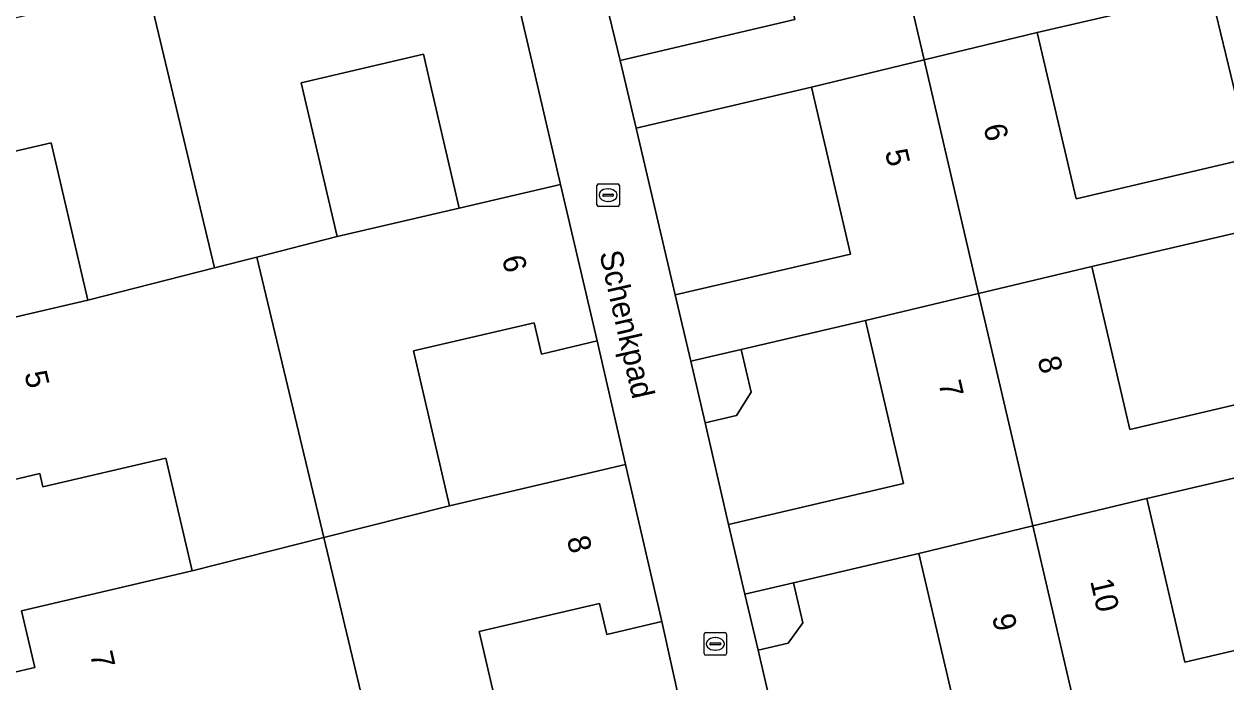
# Model space of a CAD drawing. Extents: x 162989 to 165008, y 383432 to 384338.
# Drawn here: x 164115.4 to 164168.7, y 384051 to 384080.1 of the extents above; entities that cross this region are included whole.
import ezdxf

# ---------------------------------------------------------------- set-up
doc = ezdxf.new("R2010")
doc.units = 0
for name, color, linetype in [('IMGEO_Erf', 7, 'Continuous'), ('IMGEO_Kolk', 7, 'Continuous'), ('IMGEO_Muur', 7, 'Continuous'), ('IMGEO_Openbare_ruimte_label', 7, 'Continuous'), ('IMGEO_Pand', 7, 'Continuous'), ('IMGEO_Pand_nummerreeks', 7, 'Continuous'), ('IMGEO_Voetpad_open', 7, 'Continuous')]:
    doc.layers.add(name, color=color, linetype=linetype)

msp = doc.modelspace()

# ---------------------------------------------------------------- linework, layer by layer
at = {"layer": 'IMGEO_Erf'}
for points in [[(164147.874, 384087.715), (164143.253, 384086.635), (164143.08, 384086.595), (164143.508, 384084.764), (164142.803, 384083.533), (164140.751, 384083.053), (164141.848, 384078.536), (164149.596, 384080.346)], [(164168.048, 384081.568), (164160.35, 384079.769), (164162.071, 384072.403), (164169.826, 384074.215)], [(164134.711, 384071.989), (164133.435, 384077.456), (164133.12, 384078.806), (164127.701, 384077.54), (164129.294, 384070.723)], [(164144.293, 384068.134), (164152.06, 384069.949), (164150.332, 384077.345), (164142.551, 384075.527)], [(164111.013, 384063.235), (164113.039, 384063.707), (164112.377, 384066.539), (164118.23, 384067.907), (164116.6, 384074.881), (164111.062, 384073.587), (164111.395, 384072.161), (164109.064, 384071.616)], [(164170.529, 384071.206), (164162.771, 384069.393), (164164.459, 384062.17), (164172.21, 384063.981)], [(164140.825, 384066.092), (164138.351, 384065.514), (164138.027, 384066.899), (164132.676, 384065.649), (164134.279, 384058.785), (164142.077, 384060.607)], [(164152.727, 384067.005), (164147.21, 384065.716), (164147.653, 384063.823), (164147.014, 384062.782), (164145.618, 384062.456), (164146.658, 384057.958), (164154.417, 384059.771)], [(164121.686, 384060.895), (164116.233, 384059.62), (164116.095, 384060.211), (164113.972, 384059.715), (164111.942, 384059.24), (164113.243, 384053.645), (164113.821, 384051.131), (164115.871, 384051.609), (164115.284, 384054.122), (164122.855, 384055.891)], [(164172.928, 384060.907), (164165.207, 384059.103), (164166.902, 384051.852), (164174.66, 384053.664)], [(164155.096, 384056.665), (164149.539, 384055.366), (164149.956, 384053.584), (164149.297, 384052.686), (164147.962, 384052.374), (164149.08, 384047.587), (164156.796, 384049.39)], [(164143.702, 384053.651), (164141.255, 384053.08), (164140.935, 384054.45), (164135.587, 384053.2), (164137.201, 384046.293), (164144.926, 384048.098)]]:
    msp.add_lwpolyline(points, close=True, dxfattribs=at)
at = {"layer": 'IMGEO_Kolk'}
for p, q in [((164140.813, 384072.134), (164140.813, 384072.986)), ((164140.888, 384073.06), (164141.74, 384073.06)), ((164141.072, 384072.554), (164141.072, 384072.566)), ((164141.115, 384072.603), (164141.513, 384072.603)), ((164141.301, 384072.84), (164141.326, 384072.84)), ((164141.556, 384072.566), (164141.556, 384072.554)), ((164141.814, 384072.986), (164141.814, 384072.134)), ((164141.74, 384072.06), (164140.888, 384072.06)), ((164141.51, 384072.517), (164141.112, 384072.517)), ((164141.324, 384072.28), (164141.299, 384072.28)), ((164145.567, 384052.23), (164145.567, 384053.082)), ((164145.642, 384053.156), (164146.494, 384053.156)), ((164146.055, 384052.936), (164146.08, 384052.936)), ((164146.568, 384053.082), (164146.568, 384052.23)), ((164145.826, 384052.65), (164145.826, 384052.662)), ((164146.264, 384052.613), (164145.866, 384052.613)), ((164145.869, 384052.699), (164146.267, 384052.699)), ((164146.078, 384052.376), (164146.053, 384052.376)), ((164146.31, 384052.662), (164146.31, 384052.65)), ((164146.494, 384052.156), (164145.642, 384052.156))]:
    msp.add_line(p, q, dxfattribs=at)
for points in [[(164140.813, 384072.134), (164140.813, 384072.986)], [(164140.888, 384073.06), (164141.74, 384073.06)], [(164141.814, 384072.986), (164141.814, 384072.134)], [(164141.74, 384072.06), (164140.888, 384072.06)], [(164145.567, 384052.23), (164145.567, 384053.082)], [(164145.642, 384053.156), (164146.494, 384053.156)], [(164146.568, 384053.082), (164146.568, 384052.23)], [(164146.494, 384052.156), (164145.642, 384052.156)]]:
    msp.add_lwpolyline(points, dxfattribs=at)
for centre, radius, start, end in [((164140.89, 384072.984), 0.0765, 91.552, 178.448), ((164140.89, 384072.984), 0.0765, 91.552, 178.448), ((164141.112, 384072.563), 0.0403, 85.8775, 175.7526), ((164141.109, 384072.553), 0.0366, 178.938, 274.7102), ((164141.513, 384072.56), 0.043, 264.8664, 352.4533), ((164141.517, 384072.565), 0.0386, 1.7309, 96.639), ((164141.738, 384072.984), 0.0765, 1.552, 88.448), ((164141.738, 384072.984), 0.0765, 1.552, 88.448), ((164140.89, 384072.136), 0.0765, 181.552, 268.448), ((164140.89, 384072.136), 0.0765, 181.552, 268.448), ((164141.738, 384072.136), 0.0765, 271.552, 358.448), ((164141.738, 384072.136), 0.0765, 271.552, 358.448), ((164145.644, 384053.08), 0.0765, 91.552, 178.448), ((164145.644, 384053.08), 0.0765, 91.552, 178.448), ((164146.492, 384053.08), 0.0765, 1.552, 88.448), ((164146.492, 384053.08), 0.0765, 1.552, 88.448), ((164145.866, 384052.659), 0.0403, 85.8775, 175.7526), ((164145.863, 384052.649), 0.0366, 178.938, 274.7102), ((164146.267, 384052.656), 0.043, 264.8664, 352.4533), ((164146.271, 384052.661), 0.0386, 1.7309, 96.639), ((164145.644, 384052.232), 0.0765, 181.552, 268.448), ((164145.644, 384052.232), 0.0765, 181.552, 268.448), ((164146.492, 384052.232), 0.0765, 271.552, 358.448), ((164146.492, 384052.232), 0.0765, 271.552, 358.448)]:
    msp.add_arc(centre, radius, start, end, dxfattribs=at)
for centre, major_axis, ratio, start_param, end_param in [((164141.3, 384072.56), (-0.387, 0.002), 0.722429, 4.712389, 7.853982), ((164141.325, 384072.56), (-0.39, 0.002), 0.717154, 1.570796, 4.712389), ((164146.054, 384052.656), (-0.387, 0.002), 0.722429, 4.712389, 7.853982), ((164146.079, 384052.656), (-0.39, 0.002), 0.717154, 1.570796, 4.712389)]:
    msp.add_ellipse(centre, major_axis=major_axis, ratio=ratio, start_param=start_param, end_param=end_param, dxfattribs=at)
at = {"layer": 'IMGEO_Muur'}
for points in [[(164144.979, 384065.195), (164146.658, 384057.958)], [(164147.381, 384054.862), (164149.08, 384047.587)]]:
    msp.add_lwpolyline(points, dxfattribs=at)
at = {"layer": 'IMGEO_Pand'}
for points in [[(164160.35, 384079.769), (164168.048, 384081.568), (164167.35, 384084.555), (164159.635, 384082.752), (164157.914, 384090.119), (164152.912, 384088.922), (164155.33, 384078.555)], [(164147.874, 384087.715), (164149.596, 384080.346), (164141.848, 384078.536), (164142.551, 384075.527), (164150.332, 384077.345), (164155.33, 384078.555), (164152.912, 384088.922)], [(164129.294, 384070.723), (164127.701, 384077.54), (164133.12, 384078.806), (164133.435, 384077.456), (164134.711, 384071.989), (164139.202, 384073.038), (164137.927, 384078.505), (164136.322, 384085.39), (164134.234, 384084.902), (164126.24, 384083.034), (164120.882, 384081.782), (164123.854, 384069.338), (164125.73, 384069.816)], [(164107.424, 384078.635), (164109.064, 384071.616), (164111.395, 384072.161), (164111.062, 384073.587), (164116.6, 384074.881), (164118.23, 384067.907), (164123.854, 384069.338), (164120.882, 384081.782), (164115.122, 384080.435), (164109.765, 384079.182)], [(164160.35, 384079.769), (164155.33, 384078.555), (164157.747, 384068.2), (164162.771, 384069.393), (164170.529, 384071.206), (164169.826, 384074.215), (164162.071, 384072.403)], [(164155.33, 384078.555), (164150.332, 384077.345), (164152.06, 384069.949), (164144.293, 384068.134), (164144.979, 384065.195), (164147.21, 384065.716), (164152.727, 384067.005), (164157.747, 384068.2)], [(164129.294, 384070.723), (164125.73, 384069.816), (164128.702, 384057.372), (164134.279, 384058.785), (164132.676, 384065.649), (164138.027, 384066.899), (164138.351, 384065.514), (164140.825, 384066.092), (164139.202, 384073.038), (164134.711, 384071.989)], [(164128.702, 384057.372), (164125.73, 384069.816), (164123.854, 384069.338), (164118.23, 384067.907), (164112.377, 384066.539), (164113.039, 384063.707), (164111.013, 384063.235), (164111.942, 384059.24), (164113.972, 384059.715), (164116.095, 384060.211), (164116.233, 384059.62), (164121.686, 384060.895), (164122.855, 384055.891)], [(164160.153, 384057.886), (164165.207, 384059.103), (164172.928, 384060.907), (164172.21, 384063.981), (164164.459, 384062.17), (164162.771, 384069.393), (164157.747, 384068.2)], [(164157.747, 384068.2), (164152.727, 384067.005), (164154.417, 384059.771), (164146.658, 384057.958), (164147.381, 384054.862), (164149.539, 384055.366), (164155.096, 384056.665), (164160.153, 384057.886)], [(164147.21, 384065.716), (164144.979, 384065.195), (164145.618, 384062.456), (164147.014, 384062.782), (164147.653, 384063.823)], [(164128.702, 384057.372), (164131.673, 384044.93), (164137.201, 384046.293), (164135.587, 384053.2), (164140.935, 384054.45), (164141.255, 384053.08), (164143.702, 384053.651), (164142.077, 384060.607), (164134.279, 384058.785)], [(164162.511, 384047.778), (164175.328, 384050.805), (164174.66, 384053.664), (164166.902, 384051.852), (164165.207, 384059.103), (164160.153, 384057.886)], [(164162.511, 384047.778), (164160.153, 384057.886), (164155.096, 384056.665), (164156.796, 384049.39), (164149.08, 384047.587), (164149.74, 384044.762)], [(164128.702, 384057.372), (164122.855, 384055.891), (164115.284, 384054.122), (164115.871, 384051.609), (164113.821, 384051.131), (164114.823, 384046.77), (164116.891, 384047.247), (164119.112, 384047.766), (164118.793, 384049.132), (164124.19, 384050.393), (164125.795, 384043.522), (164131.673, 384044.93)], [(164149.539, 384055.366), (164147.381, 384054.862), (164147.962, 384052.374), (164149.297, 384052.686), (164149.956, 384053.584)]]:
    msp.add_lwpolyline(points, close=True, dxfattribs=at)
at = {"layer": 'IMGEO_Voetpad_open'}
msp.add_lwpolyline([(164173.967, 384073.93), (164172.337, 384080.9), (164166.968, 384103.385), (164163.242, 384102.519), (164164.952, 384094.916), (164165.651, 384091.927), (164167.35, 384084.555), (164168.048, 384081.568), (164169.826, 384074.215), (164170.529, 384071.206), (164172.21, 384063.981), (164172.928, 384060.907), (164174.66, 384053.664), (164175.328, 384050.805), (164175.996, 384047.946), (164178.35, 384037.909), (164182.332, 384038.711), (164181.273, 384043.236), (164179.806, 384049.06), (164178.18, 384056.012), (164176.898, 384061.524), (164175.266, 384068.505)], close=True, dxfattribs=at)
msp.add_lwpolyline([(164149.08, 384047.587), (164147.962, 384052.374), (164147.381, 384054.862), (164146.658, 384057.958), (164145.618, 384062.456), (164144.979, 384065.195), (164144.293, 384068.134), (164142.551, 384075.527), (164141.848, 384078.536), (164140.751, 384083.053), (164140.088, 384085.895), (164139.377, 384088.94), (164137.621, 384096.501), (164133.948, 384095.571), (164135.568, 384088.626), (164136.322, 384085.39), (164137.927, 384078.505), (164139.202, 384073.038), (164140.825, 384066.092), (164142.077, 384060.607), (164143.702, 384053.651), (164144.926, 384048.098)], dxfattribs=at)

# ---------------------------------------------------------------- texts
at = {"layer": 'IMGEO_Openbare_ruimte_label'}
msp.add_text('Schenkpad', height=1, rotation=282.8271, dxfattribs=at).set_placement((164140.919, 384069.989))
at = {"layer": 'IMGEO_Pand_nummerreeks'}
for s, rotation, p in [('6', 283.1507, (164157.955, 384075.608)), ('5', 283.1492, (164153.588, 384074.489)), ('6', 283.1518, (164136.596, 384069.78)), ('8', 283.1538, (164160.359, 384065.3)), ('5', 283.1549, (164115.407, 384064.652)), ('7', 283.1492, (164155.964, 384064.23)), ('8', 283.1491, (164139.473, 384057.333)), ('10', 283.1572, (164162.694, 384055.444)), ('9', 283.1527, (164158.338, 384053.869)), ('7', 283.1549, (164118.32, 384052.21))]:
    msp.add_text(s, height=1, rotation=rotation, dxfattribs=at).set_placement(p)

doc.saveas('drawing.dxf')
